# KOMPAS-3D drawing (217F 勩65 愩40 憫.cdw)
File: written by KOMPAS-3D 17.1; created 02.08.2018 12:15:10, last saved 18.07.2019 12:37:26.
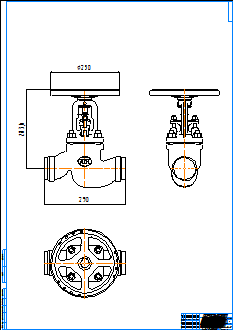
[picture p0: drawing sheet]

Sheet 1: A0, portrait

Title block, sheet 1: name: 217F Ду65 Ру40 СС; material: Внимание! Данный продукт является объектом авторского права ООО «Торговый Дом АДЛ». / Запрещается изменение, копирование, распространение / (в том числе путем копирования на другие сайты и ресурсы в Интернете) / или любое иное использование информации и объектов без предварительного / согласия правообладателя (ООО «Торговый Дом АДЛ»).; sheets: 1; organisation: ООО "Торговый дом АДЛ"; sheet format: A0; stored path: \\adlc.lan\data\АДЛ_ПКД\3D-модели\Поставщики\Zetkama\Вентили\217F\KOMPAS 2D\217F Ду65 Ру40 СС.cdw

Views: Вид 1, Проекционный вид 2, Проекционный вид 3
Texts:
  kka
  adl
Dimensions and other numbers on the sheet: 290; 283,6; 250; 1:1; 1; 217F Ду65 Ру40 СС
